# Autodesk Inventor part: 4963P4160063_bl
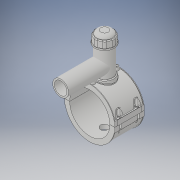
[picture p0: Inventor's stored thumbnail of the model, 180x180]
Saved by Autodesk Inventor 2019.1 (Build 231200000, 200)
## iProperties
Created: 2017-07
Part Number: 4963P4160063_bl
Material: Generic
Document SubType Name: Modeling
Designer: KIM
Density: 1 g/cm^3
Appearance: Default
Author: KIM
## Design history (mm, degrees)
derived "4963P4.ipt"
feature "Solid1::4963P4.ipt" dims "ScaleForDerivedMember" = 10
feature "Solid2::4963P4.ipt" dims "ScaleForDerivedMember" = 10
feature "Solid3::4963P4.ipt" dims "ScaleForDerivedMember" = 10
tag "TaggingFeature1"
body "Solid1"
body "Solid2"
body "Solid3"
other parameters: "d2" = 199 [user parameter], "d4" = 118 [user parameter], "d5" = 0 [user parameter], "d6" = 0.1 [user parameter], "d8" = 0 [user parameter], "d19" = 6 [user parameter], "d20" = 6 [user parameter], "d21" = 70.8 [user parameter], "d23" = 0 [user parameter], "d24" = 35.4 [user parameter], "d26" = 0 [user parameter], "d27" = 3 [user parameter], "d28" = 3 [user parameter], "d29" = 3 [user parameter], "d30" = 53.33333 [user parameter], "d31" = 6 [user parameter], "d32" = 0 [user parameter], "d33" = 0 [user parameter], "d34" = 0.6 [user parameter], "d40" = 101.504 [user parameter], "d41" = 76.8 [user parameter], "d43" = 0 [user parameter], "d45" = 0 [user parameter], "d47" = 168.4 [user parameter], "d70" = 15 [user parameter], "d72" = 0 [user parameter], "d73" = 6 [user parameter], "d75" = 5 [user parameter], "d76" = 0 [user parameter], "d77" = 8 [user parameter], "d79" = 15 [user parameter], "d80" = 47.2 [user parameter], "d82" = 5 deg [user parameter], "d84" = 4 [user parameter], "d85" = 14 [user parameter], "d86" = 0 [user parameter], "d87" = 3 [user parameter], "d88" = 0 [user parameter], "d89" = 1 [user parameter], "d90" = 1 [user parameter], "d91" = 94.4 [user parameter], "d92" = 0 [user parameter], "d93" = 0.5 [user parameter], "d94" = 84.21053 [user parameter], "d96" = 199.104 [user parameter], "d97" = 2.36 [user parameter], "d98" = 0 [user parameter], "d102" = 1.6 [user parameter], "d120" = 140 deg [user parameter], "d121" = 24.228 [user parameter], "d122" = 20 deg [user parameter], "d123" = 390.4 [user parameter], "d124" = 117.12 [user parameter], "d126" = 0 [user parameter], "d143" = 164.8 [user parameter], "d145" = 27.07692 [user parameter], "d149" = 2.4 [user parameter], "d150" = 29.78462 [user parameter], "d153" = 118 [user parameter], "d154" = 0 [user parameter], "d156" = 97.6 [user parameter], "d157" = 160 deg [user parameter], "d159" = 7.04 [user parameter], "d161" = 2.4 [user parameter], "d162" = 70.8 [user parameter], "d163" = 0 [user parameter], "d167" = 16 [user parameter], "d168" = 95.21951 [user parameter], "d170" = 3.75 [user parameter], "d172" = 0 [user parameter], "d173" = 1 [user parameter], "d176" = 20 deg [user parameter], "d177" = 11.2 [user parameter], "d178" = 35.2 [user parameter], "d180" = 0 [user parameter], "d183" = 14.08 [user parameter], "d184" = 8.96 [user parameter], "d185" = 38.35 [user parameter], "d186" = 38.35 [user parameter], "d187" = 97.6 [user parameter], "d188" = 10.56 [user parameter], "d189" = 11.2 [user parameter], "d190" = 0 [user parameter], "d191" = 146.4 [user parameter], "d193" = 8 [user parameter], "d194" = 4.13 [user parameter], "d195" = 90 deg [user parameter], "d197" = 0 [user parameter], "d199" = 0 [user parameter], "d200" = 17.6 [user parameter], "d202" = 0 [user parameter], "d203" = 177 [user parameter], "d204" = 72.96 [user parameter], "d205" = 53.76 [user parameter], "d206" = 65.28 [user parameter], "d207" = 132.75 [user parameter], "d208" = 138.06 [user parameter], "d209" = 164.61 [user parameter], "d210" = 66.048 [user parameter], "d211" = 76.8 [user parameter], "d212" = 61.44 [user parameter], "d213" = 29.25 [user parameter], "d216" = 0 [user parameter], "d217" = 16 [user parameter], "d218" = 16 [user parameter], "d219" = 3.2 [user parameter], "d224" = 0 [user parameter], "d225" = 64 [user parameter], "d226" = 63 [user parameter], "d227" = 50.4 [user parameter], "d228" = 175 [user parameter], "d230" = 3.2 [user parameter], "B_" = 199 [user parameter], "L_" = 118 [user parameter], "d_t" = 6 [user parameter], "H_2" = 177 [user parameter], "H_1" = 64 [user parameter], "d_1" = 63 [user parameter], "H_" = 175 [user parameter], "d1" = 195.2 [user parameter]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
